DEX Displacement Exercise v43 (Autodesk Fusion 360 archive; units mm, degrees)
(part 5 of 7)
sketch "Sketch38" plane through (0, 0, 0) normal (0, 0, 1) x axis (1, 0, 0)
  line L1 (44.1, 3.35) -> (-44.1, 3.35)
  line L2 (44.1, -3.35) -> (44.1, 3.35)
  line L3 (-44.1, -3.35) -> (44.1, -3.35)
  line L4 (-44.1, 3.35) -> (-44.1, -3.35)
  line L5 (3.35, -35.6) -> (-3.35, -35.6)
  line L6 (3.35, 120) -> (3.35, -35.6)
  line L7 (-3.35, 120) -> (3.35, 120)
  line L8 (-3.35, -35.6) -> (-3.35, 120)
  line L9 (0, 0) -> (-44.1, 0)
  line L10 (0, -3.35) -> (0, 0)
  line L11 (-44.2, 3.45) -> (-34.2, 3.45)
  line L12 (20, -10.75) -> (-20, -10.75)
  line L13 (20, -50.75) -> (20, -10.75)
  line L14 (-20, -50.75) -> (20, -50.75)
  line L15 (-20, -10.75) -> (-20, -50.75)
  line L16 (37.5, 19.4) -> (-37.5, 19.4)
  line L17 (37.5, -95.6) -> (37.5, 19.4)
  line L18 (-37.5, -95.6) -> (37.5, -95.6)
  line L19 (-37.5, 19.4) -> (-37.5, -95.6)
  line L20 (-34.2, 14.95) -> (-34.2, 3.45)
  line L21 (-51.5883, 14.95) -> (-34.2, 14.95)
  line L22 (-44.2, -3.35) -> (-44.2, 3.45)
  line L23 (-56.2229, -3.35) -> (-44.2, -3.35)
  line L24 (-158.6111, -137.8943) -> (-51.5883, 14.95)
  line L25 (-153.1228, -141.7373) -> (-158.6111, -137.8943)
  line L26 (-46.1, 11.107) -> (-153.1228, -141.7373)
  line L27 (-51.5883, 14.95) -> (-46.1, 11.107)
  line L28 (-149.6813, -136.8224) -> (-145.1432, -140)
  line L29 (-144.0466, -148.0925) -> (-153.1228, -141.7373)
  line L30 (-132.575, -131.7095) -> (-144.0466, -148.0925)
  line L31 (-141.6512, -125.3543) -> (-132.575, -131.7095)
  line L32 (-145.1432, -140) -> (-140.6051, -143.1776)
  line L33 (-146.8639, -142.4575) -> (-145.1432, -140)
  line L34 (-53.0452, 12.8694) -> (-47.5569, 9.0264)
  circle C1 centre (-145.1432, -140) radius 7.5
  circle C2 centre (-145.1432, -140) radius 3
  circle C3 centre (-47.5569, 9.0264) radius 0.5
  circle C4 centre (-44.2, 3.45) radius 0.5
  circle C5 centre (-145.1432, -140) radius 4
  point P10 (0, -35.6)
  point P11 (0, -3.35)
  point P12 (-44.1, 0)
  point P13 (-44.1, 0)
  point P15 (0, -3.35)
  point P1 (0, 0)
  point P14 (0, 0)
  point P22 (0, -50.75)
  point P27 (0, -95.6)
  point P5 (-44.1, -3.35)
  point P33 (-145.1432, -140)
  point P38 (-145.1432, -140)
  point P39 (-149.6813, -136.8224)
  point P40 (-147.6007, -138.2793)
  point P43 (-141.6512, -125.3543)
  point P44 (-140.6051, -143.1776)
  point P45 (-140.6051, -143.1776)
  point P46 (-145.1432, -140)
  point P32 (-145.1432, -140)
  point P47 (-145.1432, -140)
  point P48 (-146.8639, -142.4575)
  point P29 (-51.5883, 14.95)
  point P34 (-51.5883, 14.95)
  point P31 (-56.2229, -3.35)
  point P49 (-47.5569, 9.0264)
  point P50 (-53.0452, 12.8694)
  point P51 (-47.5569, 9.0264)
  point P17 (-44.2, 3.45)
  point P52 (-44.2, 3.45)
  point P6 (-3.35, -35.6)
  point P7 (3.35, -35.6)
  point P2 (-44.1, 3.35)
  point P3 (44.1, 3.35)
  point P4 (44.1, -3.35)
  point P20 (20, -50.75)
  point P21 (-20, -50.75)
  point P19 (20, -10.75)
  point P25 (37.5, -95.6)
  point P26 (-37.5, -95.6)
  point P24 (37.5, 19.4)
  point P16 (-34.2, 3.45)
  point P28 (-34.2, 14.95)
  point P37 (-46.1, 11.107)
  horizontal L1
  vertical L2
  horizontal L3
  vertical L4
  horizontal L5
  vertical L6
  horizontal L7
  vertical L8
  equal L4 L5
  midpoint L5 P10
  coincident L3 P11
  vertical P10 P11
  midpoint L4 P12
  coincident P12 P13
  perpendicular L8 L9
  perpendicular L9 L10
  coincident P11 P15
  coincident P1 P14
  midpoint L3 P11
  perpendicular L8 L11
  horizontal L12
  vertical L13
  horizontal L14
  vertical L15
  midpoint L14 P22
  vertical P1 P22
  horizontal L16
  vertical L17
  horizontal L18
  vertical L19
  midpoint L18 P27
  vertical P1 P27
  perpendicular L11 L20
  perpendicular L20 L21
  perpendicular L11 L22
  concentric C1 C2
  horizontal L23
  coincident P5 L23
  perpendicular L24 L25
  parallel L24 L26
  parallel L25 L27
  coincident P33 P38
  coincident L26 P39
  perpendicular L26 L28
  coincident C2 P40
  coincident L28 P40
  perpendicular L26 L29
  perpendicular L29 L30
  perpendicular L30 L31
  coincident L26 P43
  coincident L28 P44
  coincident P44 P45
  coincident P33 P46
  equal L28 L32
  coincident P32 P47
  coincident C2 P48
  perpendicular L28 L33
  coincident P29 P34
  coincident P31 L26
  coincident L26 P49
  coincident L24 P50
  perpendicular L24 L34
  coincident P49 P51
  coincident P17 P52
  equal C3 C4
  coincident L30 P44
  concentric C2 C5
  dimension "d1464" distance P6 P7 = 6.7 (= "t_sheet_MAIN")
  dimension "d1465" distance P10 P12 = 35.6
  dimension "d1466" distance P2 P3 = 88.2 (= "( 29.1 * 2 ) * 1 mm + 30 mm")
  dimension "d1467" distance P1 L7 = 120
  dimension "d1468" distance P4 L12 = 7.4
  dimension "d1469" distance P20 P21 = 40
  dimension "d1470" distance P19 P20 = 40
  dimension "d1471" distance P25 P26 = 75
  dimension "d1472" distance P24 P25 = 115
  dimension "d1473" distance P7 L16 = 55
  dimension "d1474" distance P12 L22 = 0.1
  dimension "d1476" distance L1 L11 = 0.1 (= "d1475")
  dimension "d1478" distance P16 P28 = 11.5
  dimension "d1489" diameter C2 = 6 (= "hw_m4insert_d")
  dimension "d1491" diameter C1 = 15
  dimension "d1502" distance L24 L26 = 6.7 (= "t_sheet_MAIN")
  dimension "d1503" = 110
  dimension "d1504" distance P1 P32 = 140
  dimension "d1506" distance L26 P40 = 2.54
  dimension "d1531" angle L15 L26 = 35
  dimension "d1532" distance P12 P37 = 2
  dimension "d1533" distance P2 L20 = 9.9
  dimension "d1541" distance P37 L34 = 2.54
  dimension "d1557" diameter C3 = 1
  dimension "d1576" distance L29 L31 = 20
  dimension "d1577" distance L29 L32 = 6
  dimension "d1583" distance C2 C5 = 1
  dimension "d1441" leftDistance = 1.7
  dimension "d1442" leftDistance = 1
  dimension "d1443" leftDistance = 0.5
  dimension "d1445" leftDistance = 0.5
  dimension "d1446" rightDistance = 1.5
  dimension "d1447" leftDistance = 0.5
  dimension "d1449" distance = 5
  dimension "d1450" distance = 15
  dimension "d1452" distance = 5
  dimension "d1453" distance = 4.9
  dimension "d1454" distance = 4.9
  dimension "d1455" distance = 5
  dimension "d1456" distance = 24.9
  dimension "d531" countU = 13 (= "nh_gantry_length + 1")
  dimension "d532" CountV = 9 (= "nh_gantry_width + 1")
  dimension "d533" uSpaceDistance = 10
  dimension "d534" vSpaceDistance = -10
  dimension "d535" diameter = 3.3 (= "hw_m4_tappedwj")
  dimension "d541" uSpaceDistance = 10
  dimension "d542" vSpaceDistance = 10
  dimension "d560" distance = 6.6 (= "t_sheet_MAIN")
  dimension "d563" distance = 5 (= "t_bearings")
  dimension "d564" distance = 16 (= "od_bearings")
  dimension "d565" angle = 45 (= "d566")
  dimension "d566" angle = 45
  dimension "d567" distance = 10 (= "l_shoulder_thread")
  dimension "d568" distance = 6.6 (= "t_sheet_MAIN")
  dimension "d569" distance = 45 (= "( ( nh_gantry_width * 10 ) * 1 mm + 10 mm ) / 2")
  dimension "d571" distance = 4.5 (= "hw_shoulder_headHeight + 0.5 mm")
  dimension "d572" distance = 4.5 (= "hw_shoulder_headDiameter / 2")
  dimension "d574" distance = 8.8037
  dimension "d576" distance = 0.5
  dimension "d577" distance = 0.5
  dimension "d580" distance = 0.5
  dimension "d581" distance = 3.5 (= "hw_m4insert_d / 2 + 0.5 mm")
  dimension "d582" distance = 3.5 (= "d581")
  dimension "d583" distance = 2.1
  dimension "d584" distance = 0.8383
  dimension "d586" distance = 1.269 (= "0.5 mm + 0.769 mm")
  dimension "d587" distance = 5
  dimension "d588" distance = 10
  dimension "d589" distance = 5
  dimension "d590" AlongDistance = 65 (= "( nh_gantry_length * 10 + 10 ) / 2 * 1 mm")
  dimension "d591" TaperAngle = 0
  dimension "d597" ProfileOffset = 0.25 (= "carriage_offsets")
  dimension "d599" TaperAngle = 0
  dimension "d601" diameter = 16 (= "od_bearings")
  dimension "d602" diameter = 6 (= "hw_m4insert_d")
  dimension "d603" diameter = 4
  dimension "d604" distance = 0.25
  dimension "d606" AlongDistance = -20
  dimension "d607" TaperAngle = 0
  dimension "d608" ProfileOffset = 0.5
  dimension "d609" AlongDistance = 5 (= "t_bearings")
  dimension "d610" TaperAngle = 0
  dimension "d612" distance = 0.25
  dimension "d613" diameter = 4
  dimension "d614" diameter = 6 (= "hw_m4insert_d")
  dimension "d615" diameter = 16 (= "od_bearings")
  dimension "d616" AlongDistance = -20
  dimension "d617" TaperAngle = 0
  dimension "d618" ProfileOffset = 0.5
  dimension "d619" AlongDistance = 5 (= "t_bearings")
  dimension "d620" TaperAngle = 0
  dimension "d621" AlongDistance = 670 (= "l_actual_complete")
  dimension "d622" TaperAngle = 0
  dimension "d623" distance = 0.1
  dimension "d624" distance = 1.6455
  dimension "d625" distance = 3.4128
  dimension "d626" distance = 13.2 (= "0.5 in + 0.5 mm")
  dimension "d628" distance = 5
  dimension "d630" distance = 30
  dimension "d631" diameter = 4.064 (= "hw_n6_thru")
  dimension "d636" diameter = 6.6548 (= "hw_n6_flathead")
  dimension "d637" diameter = 3.1 (= "hw_n6_thread")
  dimension "d638" distance = 4
  dimension "d639" distance = 4 (= "d638")
  dimension "d641" TaperAngle = 0
  dimension "d642" ProfileOffset = 0
  dimension "d643" Side1Offset = 0
  dimension "d644" TaperAngle = 0
  dimension "d645" ProfileOffset = 0
  dimension "d646" Side1Offset = 0
  dimension "d647" TaperAngle = 0
  dimension "d648" distance = 5
  dimension "d649" distance = 0.75
  dimension "d650" ProfileOffset = 0
  dimension "d651" Side1Offset = 0
  dimension "d652" TaperAngle = 0
  dimension "d653" AlongDistance = 21
  dimension "d654" TaperAngle = 0
  dimension "d655" distance = 1
  dimension "d656" ProfileOffset = 0
  dimension "d657" Side1Offset = 0
  dimension "d658" TaperAngle = 0
  dimension "d659" AlongDistance = 12
  dimension "d660" TaperAngle = 0
  dimension "d661" Side1Offset = 0
  dimension "d662" TaperAngle = 0
  dimension "d667" Radius = 4
  dimension "d669" Radius = 4
  dimension "d670" Radius = 1
  dimension "d673" Radius = 0.5
  dimension "d674" Radius = 0.5
  dimension "d675" Radius = 0.5
  dimension "d676" Radius = 0.5
  dimension "d677" Radius = 0.2
  dimension "d680" distance = 40
  dimension "d681" distance = 6
  dimension "d691" distance = 2.54
  dimension "d692" distance = 0.5 (= "d689")
  dimension "d693" distance = 0.5
  dimension "d696" distance = 0.5
  dimension "d697" distance = 5
  dimension "d701" distance = 1.7
  dimension "d702" distance = 1.7 (= "d701")
  dimension "d706" distance = 2.54 (= "d691")
  dimension "d707" distance = 3.5
  dimension "d708" distance = 0.5
  dimension "d709" ProfileOffset = 0
  dimension "d710" Side1Offset = 0
  dimension "d711" TaperAngle = 0
  dimension "d712" ProfileOffset = 0
  dimension "d713" Side1Offset = 5
  dimension "d714" TaperAngle = 0
  dimension "d715" Side1Offset = 0
  dimension "d716" TaperAngle = 0
  dimension "d717" distance = 0.75
  dimension "d718" distance = 1.7
  dimension "d719" diameter = 16 (= "od_bearings")
  dimension "d720" diameter = 6 (= "hw_m4insert_d")
  dimension "d721" diameter = 4
  dimension "d722" distance = 0.25
  dimension "d723" AlongDistance = -19
  dimension "d724" TaperAngle = 0
  dimension "d725" distance = 1
  dimension "d726" ProfileOffset = 0.5
  dimension "d727" AlongDistance = 5 (= "t_bearings")
  dimension "d728" TaperAngle = 0
  dimension "d729" diameter = 4
  dimension "d730" diameter = 6 (= "hw_m4insert_d")
  dimension "d731" diameter = 16 (= "od_bearings")
  dimension "d732" distance = 1
  dimension "d733" distance = 0.25
  dimension "d734" AlongDistance = -26
  dimension "d735" TaperAngle = 0
  dimension "d736" ProfileOffset = 0.5
  dimension "d737" AlongDistance = 5 (= "t_bearings")
  dimension "d738" TaperAngle = 0
  dimension "d739" distance = 6
  dimension "d740" ProfileOffset = 0
  dimension "d741" Side1Offset = 0
  dimension "d742" TaperAngle = 0
  dimension "d743" Radius = 4
  dimension "d744" distance = -1
  dimension "d745" AlongDistance = 32
  dimension "d746" TaperAngle = 0
  dimension "d747" distance = 0.5
  dimension "d748" distance = 1
  dimension "d749" ProfileOffset = 0
  dimension "d750" AlongDistance = 3
  dimension "d751" TaperAngle = 0
  dimension "d752" ProfileOffset = 0
  dimension "d753" Side1Offset = 0
  dimension "d754" TaperAngle = 0
  dimension "d755" Side1Offset = 0
  dimension "d756" TaperAngle = 0
  dimension "d757" ProfileOffset = 0
  dimension "d758" Side1Offset = 0
  dimension "d759" TaperAngle = 0
  dimension "d760" AlongDistance = 12
  dimension "d761" TaperAngle = 0
  dimension "d762" AlongDistance = -37
  dimension "d763" TaperAngle = 0
  dimension "d764" Side1Offset = 0.5
  dimension "d765" TaperAngle = 0
  dimension "d767" Radius = 3
  dimension "d768" Radius = 2
  dimension "d770" Radius = 3
  dimension "d771" Radius = 3
  dimension "d772" distance = 3
  dimension "d773" distance = 3
  dimension "d774" Radius = 1
  dimension "d775" Radius = 0.5
  dimension "d776" Radius = 2
  dimension "d777" diameter = 5.4 (= "hw_m3insert_d")
  dimension "d778" diameter = 3.5 (= "hw_m3_thru")
  dimension "d779" Side1Offset = 0
  dimension "d780" TaperAngle = 0
  dimension "d781" Side1Offset = 0
  dimension "d782" TaperAngle = 0
  dimension "d783" Radius = 2
  dimension "d784" Radius = 2
  dimension "d785" Radius = 2
  dimension "d786" Radius = 3
  dimension "d788" Radius = 0.5
  dimension "d789" distance = 12
  dimension "d790" distance = 2
  dimension "d791" angle = 45
  dimension "d793" Radius = 2
  dimension "d794" Radius = 2
  dimension "d795" Radius = 1
  dimension "d797" Radius = 2
  dimension "d798" Radius = 1
  dimension "d799" Radius = 2
  dimension "d800" Radius = 4.5
  dimension "d801" distance = 0.275 (= "preload_bearings / 2")
  dimension "d803" distance = -0.5
  dimension "d806" distance = 3
  dimension "d807" AlongDistance = -60
  dimension "d808" distance = 3.8274 (= "d430 / 2")
  dimension "d809" distance = 0.423 (= "1 mm - 0.577 mm")
  dimension "d810" distance = 0.5
  dimension "d813" Side1Offset = 0
  dimension "d814" TaperAngle = 0
  dimension "d815" distance = 0.1
  dimension "d816" distance = 1.75
  dimension "d818" distance = 35
  dimension "d820" distance = 5
  dimension "d821" distance = 5
  dimension "d822" diameter = 4.064 (= "hw_n6_thru")
  dimension "d823" diameter = 6.6548 (= "hw_n6_flathead")
  dimension "d824" distance = 0.6
  dimension "d825" distance = 0.6 (= "d824")
  dimension "d827" TaperAngle = 0
  dimension "d828" diameter = 3.1 (= "hw_n6_thread")
  dimension "d829" Side1Offset = 0
  dimension "d830" TaperAngle = 0
  dimension "d831" distance = 4
  dimension "d832" distance = 4.477 (= "d833")
  dimension "d833" distance = 4.477 (= "d477")
  dimension "d836" diameter = 6.6548 (= "hw_n6_flathead")
  dimension "d839" Side1Offset = 0
  dimension "d840" TaperAngle = 0
  dimension "d841" distance = 0.9
  dimension "d842" angle = 50
  dimension "d843" angle = 50
  dimension "d844" distance = 8
  dimension "d845" distance = 5
  dimension "d846" diameter = 4.5
  dimension "d847" AlongDistance = -7
  dimension "d848" TaperAngle = 0
  dimension "d849" leftDistance = 0.75
  dimension "d850" ProfileOffset = 0
  dimension "d851" Side1Offset = 0
  dimension "d852" TaperAngle = 0
  dimension "d853" ProfileOffset = 0
  dimension "d854" Side1Offset = 0
  dimension "d855" TaperAngle = 0
  dimension "d856" distance = 12.7
  dimension "d857" leftDistance = 1.5
  dimension "d858" distance = 1.5454
  dimension "d859" Radius = 4
  dimension "d860" Radius = 2
  dimension "d861" Radius = 2
  dimension "d862" Radius = 4
  dimension "d863" Radius = 2
  dimension "d864" Radius = 35
  dimension "d865" Radius = 4
  dimension "d866" Radius = 1
  dimension "d869" Side1Offset = 0
  dimension "d870" TaperAngle = 0
  dimension "d872" distance = 1.5
  dimension "d873" leftDistance = 1.5
  dimension "d874" Radius = 2
  dimension "d885" distance = 27.775
  dimension "d886" distance = 30.275 (= "30 mm + preload_bearings / 2")
  dimension "d889" diameter = 3.3 (= "hw_m4_tappedwj")
  dimension "d890" distance = 5
  dimension "d891" distance = 10.275 (= "10 mm + preload_bearings / 2")
  dimension "d893" TaperAngle = 0
  dimension "d894" distance = 17.5
  dimension "d895" distance = 27.5
  dimension "d896" distance = 0.2
  dimension "d897" distance = 0.2 (= "d896")
  dimension "d900" distance = 6
  dimension "d902" distance = 3.7 (= "2 mm + 1.2 mm + 0.5 mm")
  dimension "d903" distance = 1
  dimension "d904" distance = 8
  dimension "d905" distance = 2.54
  dimension "d906" distance = 2.54
  dimension "d907" distance = 2.54
  dimension "d908" Side1Offset = 0
  dimension "d909" TaperAngle = 0
  dimension "d910" ProfileOffset = 0
  dimension "d911" Side1Offset = 0
  dimension "d912" TaperAngle = 0
  dimension "d913" leftDistance = 1.5
  dimension "d915" distance = 5.65
  dimension "d916" distance = 14.65
  dimension "d917" distance = 14.65
  dimension "d918" Side1Offset = 0
  dimension "d919" TaperAngle = 0
  dimension "d920" ChordLen = 4
  dimension "d921" ChordLen = 1
  dimension "d923" distance = 2.54
  dimension "d924" Radius = 2
extrude "Extrude159" new body sketch "Sketch38" profile of L11 L20 L21 L22 L23 L24 L26 L27 L34 C3 C4 along normal blind 40
extrude "Extrude160" sketch "Sketch38" profile of C1 L24 L25 L26 L34 to an object offset -25
sketch "Sketch40" plane through (-41.6405, 29.157, 0) normal (-0.8192, 0.5736, 0) x axis (-0.5736, -0.8192, 0)
  line L1 (203.932, -25) -> (19.8835, -25)
  line L2 (203.932, 40) -> (203.932, -25)
  line L3 (183.932, -5) -> (203.932, -5)
  line L4 (34.9923, 40) -> (183.932, -5)
  line L5 (183.932, -25) -> (17.3435, 0)
  line L6 (34.9923, 40) -> (34.9923, 0)
  line L7 (183.932, -25) -> (183.932, -5)
  line L8 (19.8835, 40) -> (203.932, 40)
  line L9 (19.8835, -25) -> (19.8835, 40)
  point P7 (203.932, -5)
  point P4 (17.3435, 0)
  point P10 (17.3435, 0)
  point P11 (183.932, -25)
  point P8 (183.932, -5)
  point P9 (34.9923, 40)
  point P13 (34.9923, 40)
  point P6 (203.932, -25)
  coincident L2 P7
  perpendicular L2 L3
  coincident P4 P10
  coincident L1 P11
  vertical P8 P11
  coincident P9 P13
  dimension "d1521" distance P6 P11 = 20
  dimension "d1522" distance P6 L3 = 20
extrude "Extrude161" cut sketch "Sketch40" profile of L1 L2 L3 L4 L5 along a picked direction no distance stored
extrude "Extrude162" sketch "Sketch40" profile of L1 L2 L3 L7 to an object
extrude "Extrude163" sketch "Sketch38" profile of C1 C2 L26 L30 blind -15 from offset -0.5
sketch "Sketch41" plane through (0, 3.45, 0) normal (0, -1, 0) x axis (1, 0, 0)
  line L1 (-34.2, 0) -> (-43.7, 0)
  line L2 (-34.2, 40) -> (-34.2, 0)
  line L3 (-43.7, 40) -> (-34.2, 40)
  line L4 (-43.7, 0) -> (-43.7, 40)
  circle C1 centre (-39.1, 5) radius 2.7
  circle C2 centre (-39.1, 35) radius 2.7
  point P6 (-39.1, 5)
  point P7 (-39.1, 35)
  vertical P6 P7
  equal C1 C2
  dimension "d1534" distance L3 P7 = 5
  dimension "d1536" distance L1 P6 = 5
  dimension "d1537" = 20
  dimension "d1538" diameter C2 = 5.4 (= "hw_m3insert_d")
extrude "Extrude164" cut sketch "Sketch41" profile of C1 C2 to an object
sketch "Sketch42" plane through (-36.1522, 25.314, 0) normal (-0.8192, 0.5736, 0) x axis (-0.5736, -0.8192, 0)
  line L1 (34.9923, 0) -> (20.3835, 0)
  line L2 (34.9923, 40) -> (34.9923, 0)
  line L3 (20.3835, 40) -> (34.9923, 40)
  line L4 (20.3835, 0) -> (20.3835, 40)
  circle C1 centre (27.9923, 35) radius 2.7
  circle C2 centre (27.9923, 5) radius 2.7
  circle C3 centre (27.9923, 5) radius 1.575
  circle C4 centre (27.9923, 35) radius 1.575
  point P6 (27.9923, 35)
  point P7 (27.9923, 5)
  vertical P6 P7
  equal C1 C2
  concentric C2 C3
  concentric C1 C4
  equal C3 C4
  dimension "d1544" distance L3 P6 = 5
  dimension "d1545" distance L1 P7 = 5
  dimension "d1546" distance L2 P7 = 7
  dimension "d1547" diameter C1 = 5.4 (= "hw_m3insert_d")
  dimension "d1548" diameter C4 = 3.15
extrude "Extrude165" cut sketch "Sketch42" profile of C1 C2 C3 C4 along a picked direction blind -6
chamfer "Chamfer37" distance 0.5
extrude "Extrude166" cut sketch "Sketch42" profile of C3 C4 along a picked direction blind 6.7 (= "t_sheet_MAIN")
fillet "Fillet111" radius 4
fillet "Fillet112" radius 2
fillet "Fillet113" radius 2
fillet "Fillet114" radius 0.4
fillet "Fillet115" radius 0.4
sketch "Sketch43" plane through (-27.076, 18.9588, 0) normal (0.8192, -0.5736, 0) x axis (0.5736, 0.8192, 0)
  line L1 (-183.932, -25) -> (-203.932, -25)
  line L2 (-183.932, -5) -> (-183.932, -25)
  line L3 (-203.932, -5) -> (-183.932, -5)
  line L4 (-203.932, -25) -> (-203.932, -5)
  circle C1 centre (-188.932, -20) radius 2.7
  circle C2 centre (-198.932, -10) radius 2.7
  circle C3 centre (-188.932, -20) radius 1.575
  circle C4 centre (-198.932, -10) radius 1.575
  point P8 (-188.932, -20)
  point P9 (-198.932, -10)
  point P6 (-188.932, -20)
  point P7 (-198.932, -10)
  equal C1 C2
  concentric C1 C3
  concentric C2 C4
  equal C3 C4
  dimension "d1560" diameter C1 = 5.4 (= "hw_m3insert_d")
  dimension "d1561" diameter C3 = 3.15
  dimension "d1563" distance L1 P8 = 5 (= "d1562")
  dimension "d1565" distance L3 P9 = 5
  dimension "d1578" distance L2 P6 = 5
  dimension "d1579" distance L4 P7 = 5
extrude "Extrude167" cut sketch "Sketch43" profile of C3 C4 along a picked direction to an object
extrude "Extrude168" cut sketch "Sketch43" profile of C1 C2 C3 C4 along a picked direction blind -6
chamfer "Chamfer38" distance 1
chamfer "Chamfer39" distance 0.5
extrude "Extrude170" sketch "Sketch38" profile of C2 blind 11
extrude "Extrude171" sketch "Sketch38" profile of C2 C5 blind -0.5
combine "Combine23"
chamfer "Chamfer40" distance 0.5
chamfer "Chamfer41" distance 0.5
fillet "Fillet116" radius 2
fillet "Fillet117" radius 1
mirror "Mirror13"

design "rct-lb-gt3-endmatter"
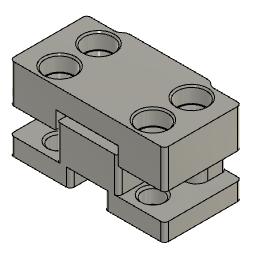
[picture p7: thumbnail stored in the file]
parameter "t_sheet_MAIN" = 6.7 comment "thickness of *most* of the gantry material"
parameter "t_sheet_SECOND" = 6.35 (= "1 / 4 * 1") comment "thickness of the webs"
parameter "od_bearings" = 16
parameter "id_bearings" = 5
parameter "t_bearings" = 5
parameter "p_belt" = 2
parameter "w_belt" = 10
parameter "t_belt" = 1.4
parameter "l_top_belt_to_rail" = 3
parameter "r_cutoutTool" = 2.05 (= "4.1 mm / 2")
parameter "hw_m3_thru" = 3.5
parameter "hw_m3_head" = 5.5
parameter "hw_m3_washer" = 7
parameter "hw_m3_thread" = 2.5
parameter "tab_breather" = 0.2 comment "tab clearance"
parameter "hw_m5_thread" = 4.2
parameter "hw_m5_head" = 8.5
parameter "hw_m5_washer" = 10
parameter "hw_m5_thru" = 5.25
parameter "hw_m6_thru" = 6.5
parameter "hw_m6_head" = 10
parameter "hw_m6_washer" = 12
parameter "l_beltblock" = 15
parameter "hw_plstf6_thread" = 2.94
parameter "hw_plstf6_thru" = 4
parameter "hw_plstf6_head" = 6.86
parameter "hw_plstf6_washer" = 7.92
parameter "hw_m3_flathead" = 6
parameter "hw_m4insert_d" = 6
parameter "hw_m4insert_l" = 4.8
parameter "hw_m4_tappedwj" = 3.3
parameter "hw_m4_thru" = 4.25
parameter "hw_m4_head" = 7
parameter "hw_m4_headheight" = 4
parameter "preload_bearings" = 0.55
parameter "hw_m3insert_d" = 5.4
parameter "hw_m3insert_l" = 3.8
parameter "dist_clearance" = 0.5
parameter "hw_shoulder_headDiameter" = 9
parameter "hw_shoulder_headHeight" = 4
parameter "l_travel" = 405 comment "will be rounded to 10s"
parameter "User Parameter" = 0 (= "min 10")
parameter "nh_rail_width" = "nh_gantry_width - 3"
parameter "l_shoulder_thread" = 10
parameter "hw_n6_thru" = 4.064
parameter "hw_n6_thread" = 3.1
parameter "hw_n6_flathead" = 6.6548
parameter "hw_n6_head" = 6.858
parameter "carriage_offsets" = 0.25
parameter "hw_momentPin_reald" = 3.683
parameter "pinch_by" = 0.2
parameter "d285" = 2
parameter "d344" = 3.5
parameter "d482" = 3.35 (= "t_sheet_MAIN / 2")
parameter "d578" = 0.5
parameter "d683" = 3.683 (= "hw_momentPin_reald")
parameter "d689" = 0.5
parameter "d698" = 5
parameter "d705" = 3.5415 (= "d683 / 2 + 1.7 mm")
parameter "d837" = 0.25
sketch "Sketch32" plane through (0, 0, 0) normal (0, 0, 1) x axis (1, 0, 0)
  line L1 (19.9, 0) -> (0, 0)
  line L2 (19.9, 21) -> (19.9, 0)
  line L3 (0, 21) -> (19.9, 21)
  line L4 (0, 0) -> (0, 21)
  line L5 (7.5, 0) -> (7.5, 21)
  line L6 (8, 12) -> (19.9, 12)
  line L7 (8, 0) -> (8, 12)
  line L8 (16, 21) -> (16, 12)
  line L9 (12, 19.8) -> (19.9, 19.8)
  line L10 (10.8, 21) -> (12, 19.8)
  circle C1 centre (12, 4.9) radius 2.7
  circle C2 centre (12, 14.9) radius 2.7
  circle C3 centre (12, 14.9) radius 1.575
  circle C4 centre (12, 4.9) radius 1.575
  circle C5 centre (12, 4.9) radius 3.75
  circle C6 centre (12, 14.9) radius 3.75
  point P1 (0, 0)
  point P2 (0, 0)
  point P6 (7.5, 21)
  point P7 (7.5, 0)
  point P8 (12, 4.9)
  point P9 (12, 14.9)
  point P12 (8, 0)
  point P10 (19.9, 12)
  point P15 (12, 13.325)
  point P13 (12, 14.9)
  point P16 (16, 12)
  point P17 (16, 21)
  point P20 (19.9, 19.8)
  point P22 (10.8, 21)
  point P19 (12, 14.9)
  point P21 (12, 19.8)
  point P3 (19.9, 0)
  horizontal L1
  vertical L2
  horizontal L3
  vertical L4
  coincident P1 P2
  coincident L3 P6
  coincident L1 P7
  perpendicular L1 L5
  equal C1 C2
  vertical P8 P9
  perpendicular L2 L6
  coincident L1 P12
  perpendicular L1 L7
  concentric C2 C3
  concentric C1 C4
  equal C3 C4
  coincident L2 P10
  coincident C3 P15
  vertical P13 P15
  coincident L6 P16
  coincident L3 P17
  perpendicular L3 L8
  concentric C4 C5
  concentric C3 C6
  equal C5 C6
  coincident L2 P20
  perpendicular L8 L9
  coincident L3 P22
  vertical P19 P21
  dimension "d1252" distance P1 L5 = 7.5 (= "( 15 / 2 ) * 1 mm")
  dimension "d1253" diameter C2 = 5.4 (= "hw_m3insert_d")
  dimension "d1254" distance P1 P8 = 12
  dimension "d1255" distance P1 L2 = 19.9 (= "( 39.8 / 2 ) * 1 mm")
  dimension "d1256" distance L5 L7 = 0.5
  dimension "d1257" distance P8 P9 = 10
  dimension "d1258" distance P3 P8 = 4.9
  dimension "d1259" = 4.9
  dimension "d1260" diameter C3 = 3.15
  dimension "d1261" = 1.7
  dimension "d1262" distance P1 L8 = 16
  dimension "d1272" diameter C6 = 7.5
  dimension "d1304" distance P1 L3 = 21 (= "( 3 * 7 ) * 1 mm")
  dimension "d1306" distance P19 L9 = 4.9
  dimension "d1307" angle L9 L10 = 45
  dimension "d1326" distance P3 L6 = 12
  dimension "d485" distance = 0.75 (= "d480")
  dimension "d487" diameter = 3.1 (= "hw_n6_thread")
  dimension "d488" diameter = 4.064 (= "hw_n6_thru")
  dimension "d497" distance = 9
  dimension "d498" angle = 5 (= "d469")
  dimension "d500" distance = 5
  dimension "d501" radius = 11.075 (= "( 22.15 / 2 ) * 1 mm")
  dimension "d504" diameter = 5.3 (= "hw_m3insert_d - 0.1 mm")
  dimension "d506" diameter = 3.5 (= "hw_m3_thru")
  dimension "d535" diameter = 3.3 (= "hw_m4_tappedwj")
  dimension "d560" distance = 6.6 (= "t_sheet_MAIN")
  dimension "d563" distance = 5 (= "t_bearings")
  dimension "d564" distance = 16 (= "od_bearings")
  dimension "d565" angle = 45 (= "d566")
  dimension "d566" angle = 45
  dimension "d567" distance = 10 (= "l_shoulder_thread")
  dimension "d568" distance = 6.6 (= "t_sheet_MAIN")
  dimension "d569" distance = 45 (= "( ( nh_gantry_width * 10 ) * 1 mm + 10 mm ) / 2")
  dimension "d571" distance = 4.5 (= "hw_shoulder_headHeight + 0.5 mm")
  dimension "d572" distance = 4.5 (= "hw_shoulder_headDiameter / 2")
  dimension "d574" distance = 8.8037
  dimension "d576" distance = 0.5
  dimension "d577" distance = 0.5
  dimension "d580" distance = 0.5
  dimension "d581" distance = 3.5 (= "hw_m4insert_d / 2 + 0.5 mm")
  dimension "d582" distance = 3.5 (= "d581")
  dimension "d583" distance = 2.1
  dimension "d584" distance = 0.8383
  dimension "d586" distance = 1.269 (= "0.5 mm + 0.769 mm")
  dimension "d587" distance = 5
  dimension "d588" distance = 10
  dimension "d589" distance = 5
  dimension "d601" diameter = 16 (= "od_bearings")
  dimension "d602" diameter = 6 (= "hw_m4insert_d")
  dimension "d603" diameter = 4
  dimension "d604" distance = 0.25
  dimension "d612" distance = 0.25
  dimension "d613" diameter = 4
  dimension "d614" diameter = 6 (= "hw_m4insert_d")
  dimension "d615" diameter = 16 (= "od_bearings")
  dimension "d623" distance = 0.1
  dimension "d624" distance = 1.6455
  dimension "d625" distance = 3.4128
  dimension "d626" distance = 13.2 (= "0.5 in + 0.5 mm")
  dimension "d628" distance = 5
  dimension "d630" distance = 30
  dimension "d631" diameter = 4.064 (= "hw_n6_thru")
  dimension "d636" diameter = 6.6548 (= "hw_n6_flathead")
  dimension "d637" diameter = 3.1 (= "hw_n6_thread")
  dimension "d638" distance = 4
  dimension "d639" distance = 4 (= "d638")
  dimension "d648" distance = 5
  dimension "d649" distance = 0.75
  dimension "d655" distance = 1
  dimension "d680" distance = 40
  dimension "d681" distance = 6
  dimension "d691" distance = 2.54
  dimension "d692" distance = 0.5 (= "d689")
  dimension "d693" distance = 0.5
  dimension "d696" distance = 0.5
  dimension "d697" distance = 5
  dimension "d701" distance = 1.7
  dimension "d702" distance = 1.7 (= "d701")
  dimension "d706" distance = 2.54 (= "d691")
  dimension "d707" distance = 3.5
  dimension "d708" distance = 0.5
  dimension "d717" distance = 0.75
  dimension "d718" distance = 1.7
  dimension "d719" diameter = 16 (= "od_bearings")
  dimension "d720" diameter = 6 (= "hw_m4insert_d")
  dimension "d721" diameter = 4
  dimension "d722" distance = 0.25
  dimension "d725" distance = 1
  dimension "d729" diameter = 4
  dimension "d730" diameter = 6 (= "hw_m4insert_d")
  dimension "d731" diameter = 16 (= "od_bearings")
  dimension "d732" distance = 1
  dimension "d733" distance = 0.25
  dimension "d739" distance = 6
  dimension "d747" distance = 0.5
  dimension "d748" distance = 1
  dimension "d777" diameter = 5.4 (= "hw_m3insert_d")
  dimension "d778" diameter = 3.5 (= "hw_m3_thru")
  dimension "d789" distance = 12
  dimension "d790" distance = 2
  dimension "d791" angle = 45
  dimension "d801" distance = 0.275 (= "preload_bearings / 2")
  dimension "d806" distance = 3
  dimension "d807" AlongDistance = -60
  dimension "d808" distance = 3.8274 (= "d430 / 2")
  dimension "d809" distance = 0.423 (= "1 mm - 0.577 mm")
  dimension "d810" distance = 0.5
  dimension "d815" distance = 0.1
  dimension "d816" distance = 1.75
  dimension "d818" distance = 35
  dimension "d820" distance = 5
  dimension "d821" distance = 5
  dimension "d822" diameter = 4.064 (= "hw_n6_thru")
  dimension "d823" diameter = 6.6548 (= "hw_n6_flathead")
  dimension "d824" distance = 0.6
  dimension "d825" distance = 0.6 (= "d824")
  dimension "d828" diameter = 3.1 (= "hw_n6_thread")
  dimension "d831" distance = 4
  dimension "d832" distance = 4.477 (= "d833")
  dimension "d833" distance = 4.477 (= "d477")
  dimension "d836" diameter = 6.6548 (= "hw_n6_flathead")
  dimension "d841" distance = 0.9
  dimension "d842" angle = 50
  dimension "d843" angle = 50
  dimension "d844" distance = 8
  dimension "d845" distance = 5
  dimension "d846" diameter = 4.5
  dimension "d856" distance = 12.7
  dimension "d858" distance = 1.5454
  dimension "d872" distance = 1.5
  dimension "d885" distance = 27.775
  dimension "d886" distance = 30.275 (= "30 mm + preload_bearings / 2")
  dimension "d889" diameter = 3.3 (= "hw_m4_tappedwj")
  dimension "d890" distance = 5
  dimension "d891" distance = 10.275 (= "10 mm + preload_bearings / 2")
  dimension "d894" distance = 17.5
  dimension "d895" distance = 27.5
  dimension "d896" distance = 0.2
  dimension "d897" distance = 0.2 (= "d896")
  dimension "d900" distance = 6
  dimension "d902" distance = 3.7 (= "2 mm + 1.2 mm + 0.5 mm")
  dimension "d903" distance = 1
  dimension "d904" distance = 8
  dimension "d905" distance = 2.54
  dimension "d906" distance = 2.54
  dimension "d907" distance = 2.54
  dimension "d915" distance = 5.65
  dimension "d916" distance = 14.65
  dimension "d917" distance = 14.65
  dimension "d923" distance = 2.54
extrude "Extrude131" new body sketch "Sketch32" profile of L1 L2 L3 L4 C1 C2 L6 L7 C3 C4 L8 C5 C6 L9 L10 along normal blind 4.5
extrude "Extrude132" sketch "Sketch32" profile of L1 L3 L4 C2 L6 L7 C3 L8 C6 L9 L10 blind 6.7 (= "t_sheet_MAIN")
extrude "Extrude133" sketch "Sketch32" profile of L1 L2 L3 L4 C1 C2 L6 L7 C3 C4 L8 C5 C6 L9 L10 blind 10
extrude "Extrude134" cut sketch "Sketch32" profile of C3 C4 no distance stored
extrude "Extrude135" sketch "Sketch32" profile of C1 C2 L6 C3 C4 C5 C6 blind -4
extrude "Extrude136" cut sketch "Sketch32" profile of C1 C2 C3 C4 along normal blind 4.5
sketch "Sketch33" plane through (0, 0, 0) normal (-1, 0, 0) x axis (0, -1, 0)
  line L1 (0, 0) -> (-21, 0)
  line L2 (0, 21.2) -> (0, 0)
  line L3 (-21, 0) -> (-21, 21.2)
  line L4 (-19.8, 4.5) -> (0, 4.5)
  line L5 (0, 13.5) -> (-21, 13.5)
  line L6 (-21, 21.2) -> (0, 21.2)
  line L7 (-19.5, 14.76) -> (-19.8489, 14.76)
  line L8 (-19.5, 13.5) -> (-19.5, 14.76)
  line L9 (-12, 11.2) -> (0, 11.2)
  line L10 (-21, 11.2) -> (-12, 11.2)
  line L11 (-21, 11.3) -> (0, 11.3)
  line L12 (-21, 4.5) -> (-19.8, 4.5)
  arc A1 centre (-21, 15.05) radius 0.85 clockwise from (-21, 15.9) to (-20.2388, 15.4283)
  arc A2 centre (-19.8489, 15.01) radius 0.25 clockwise from (-19.8489, 14.76) to (-20.0963, 14.9735)
  arc A3 centre (-21.6, 14.7518) radius 1.52 clockwise from (-20.2388, 15.4283) to (-20.0963, 14.9735)
  point P8 (-21, 13.5)
  point P9 (0, 13.5)
  point P10 (-21, 15.9)
  point P12 (-21, 15.05)
  point P15 (-19.5, 13.5)
  point P11 (-20.2388, 15.4283)
  point P18 (-20.2388, 15.4283)
  point P16 (-20.0963, 14.9735)
  point P19 (-20.0963, 14.9735)
  point P22 (-12, 11.2)
  point P23 (-12, 11.2)
  point P24 (-21, 11.2)
  point P25 (0, 11.3)
  point P26 (-21, 11.3)
  point P7 (-19.8, 4.5)
  point P27 (-19.8, 4.5)
  point P28 (-21, 4.5)
  point P14 (-19.5, 14.76)
  point P20 (-21.6, 14.7518)
  coincident L3 P8
  coincident L2 P9
  perpendicular L2 L5
  coincident L3 P10
  coincident L3 P12
  horizontal L7
  coincident L5 P15
  perpendicular L5 L8
  tangent L7 A2
  coincident P11 P18
  coincident P16 P19
  tangent A2 A3
  tangent A1 A3
  coincident P22 P23
  perpendicular L3 L10
  coincident L3 P24
  coincident L2 P25
  coincident L3 P26
  perpendicular L3 L11
  coincident P7 P27
  coincident L3 P28
  perpendicular L3 L12
  dimension "d1285" distance P7 L5 = 9
  dimension "d1286" distance L5 P10 = 2.4
  dimension "d1287" radius A1 = 0.85
  dimension "d1288" distance P8 L8 = 1.5
  dimension "d1291" radius A2 = 0.25
  dimension "d1293" distance P10 P14 = 1.14
  dimension "d1295" radius A3 = 1.52
  dimension "d1296" distance L3 P20 = 0.6
  dimension "d1308" distance L10 L11 = 0.1
extrude "Extrude138" new body sketch "Sketch33" profile of L3 L5 A1 L7 L8 A2 A3 against normal blind 8
extrude "Extrude137" cut sketch "Sketch33" profile of L1 L2 L3 L4 L12 against normal blind 4.35 (magnitude of "-t_sheet_MAIN / 2 - 1 mm")
mirror "Mirror8"
combine "Combine17"
rectangular_pattern "R-Pattern4" uSpaceDistance -3 vSpaceDistance 0
combine "Combine18"
combine "Combine19"
extrude "Extrude139" sketch "Sketch33" profile of L2 L3 L9 L10 L11 no distance stored
extrude "Extrude140" sketch "Sketch33" profile of L2 L3 L5 L9 L10 L11 blind 0.1
fillet "Fillet94" radius 3
fillet "Fillet95" radius 2
chamfer "Chamfer16" distance 0.9
chamfer "Chamfer17" distance 0.5
chamfer "Chamfer18" distance 0.5
chamfer "Chamfer19" distance 1.9
chamfer "Chamfer20" distance 0.4
mirror "Mirror9"
combine "Combine20"
combine "Combine21"
fillet "Fillet96" radius 1
fillet "Fillet97" radius 1
chamfer "Chamfer21" distance 0.2
chamfer "Chamfer22" distance 0.2
chamfer "Chamfer14" distance 0.9
fillet "Fillet93" radius 3
chamfer "Chamfer15" distance 0.5
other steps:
fillet "Extrude48" AlongDistance 65 (= "( nh_gantry_length * 10 + 10 ) / 2 * 1 mm") TaperAngle 0
fillet "Extrude57" TaperAngle 0
fillet "Extrude51" ProfileOffset 0.25 (= "carriage_offsets") TaperAngle 0
fillet "Extrude52" AlongDistance -20 TaperAngle 0
fillet "Extrude53" ProfileOffset 0.5 AlongDistance 5 (= "t_bearings") TaperAngle 0
fillet "Extrude54" AlongDistance -20 TaperAngle 0
fillet "Extrude55" ProfileOffset 0.5 AlongDistance 5 (= "t_bearings") TaperAngle 0
fillet "Extrude56" AlongDistance 670 (= "l_actual_complete") TaperAngle 0
fillet "Extrude58" ProfileOffset 0 Side1Offset 0 TaperAngle 0
fillet "Extrude59" ProfileOffset 0 Side1Offset 0 TaperAngle 0
fillet "Extrude60" ProfileOffset 0 Side1Offset 0 TaperAngle 0
step "Fillet30" Radius 4
fillet "Extrude61" AlongDistance 21 TaperAngle 0
step "OffsetFaces6"
fillet "Extrude62" ProfileOffset 0 Side1Offset 0 TaperAngle 0
fillet "Extrude63" AlongDistance 12 TaperAngle 0
step "Fillet31" Radius 4
step "Fillet32" Radius 1
step "Fillet35" Radius 0.5
step "Fillet36" Radius 0.5
step "Fillet37" Radius 0.5
step "Fillet38" Radius 0.5
step "Fillet39" Radius 0.2
step "OffsetFaces9" distance 3
step "Fillet63" Radius 2
step "Fillet64" Radius 1
fillet "Extrude64" Side1Offset 0 TaperAngle 0
fillet "Extrude65" ProfileOffset 0 Side1Offset 0 TaperAngle 0
fillet "Extrude66" ProfileOffset 0 Side1Offset 5 TaperAngle 0
fillet "Extrude67" Side1Offset 0 TaperAngle 0
fillet "Extrude68" AlongDistance -19 TaperAngle 0
fillet "Extrude69" ProfileOffset 0.5 AlongDistance 5 (= "t_bearings") TaperAngle 0
fillet "Extrude70" AlongDistance -26 TaperAngle 0
fillet "Extrude71" ProfileOffset 0.5 AlongDistance 5 (= "t_bearings") TaperAngle 0
fillet "Extrude74" ProfileOffset 0 AlongDistance 3 TaperAngle 0
fillet "Extrude75" ProfileOffset 0 Side1Offset 0 TaperAngle 0
fillet "Extrude76" Side1Offset 0 TaperAngle 0
fillet "Extrude77" ProfileOffset 0 Side1Offset 0 TaperAngle 0
fillet "Extrude78" AlongDistance 12 TaperAngle 0
fillet "Extrude72" ProfileOffset 0 Side1Offset 0 TaperAngle 0
step "Fillet42" Radius 4
step "OffsetFaces7" distance -1
fillet "Extrude73" AlongDistance 32 TaperAngle 0
fillet "Extrude79" AlongDistance -37 TaperAngle 0
fillet "Extrude80" Side1Offset 0.5 TaperAngle 0
step "Fillet44" Radius 3
step "Fillet45" Radius 2
step "Fillet47" Radius 3
step "Fillet48" Radius 3
step "Fillet49" Radius 1
step "Fillet50" Radius 0.5
step "Fillet51" Radius 2
step "Fillet55" Radius 3
step "Fillet57" Radius 0.5
fillet "Extrude81" Side1Offset 0 TaperAngle 0
fillet "Extrude82" Side1Offset 0 TaperAngle 0
step "Fillet52" Radius 2
step "Fillet53" Radius 2
step "Fillet54" Radius 2
step "OffsetFaces8" distance 3
step "Fillet59" Radius 2
step "Fillet60" Radius 2
step "Fillet61" Radius 1
step "Fillet65" Radius 2
step "Fillet66" Radius 4.5
step "OffsetFaces10" distance -0.5
fillet "Extrude83" Side1Offset 0 TaperAngle 0
fillet "Extrude84" TaperAngle 0
fillet "Extrude85" Side1Offset 0 TaperAngle 0
fillet "Extrude86" Side1Offset 0 TaperAngle 0
fillet "Extrude40" Side1Offset 0 TaperAngle 0
fillet "Extrude93" Side1Offset 0 TaperAngle 0
fillet "Extrude94" ProfileOffset 0 Side1Offset 0 TaperAngle 0
step "Chamfer8" leftDistance 1.5
fillet "Extrude95" Side1Offset 0 TaperAngle 0
fillet "Extrude41" Side1Offset 0 TaperAngle 0
fillet "Extrude87" AlongDistance -7 TaperAngle 0
step "Chamfer5" leftDistance 0.75
fillet "Extrude42" AlongDistance -5 TaperAngle 0
fillet "Extrude36" Side1Offset 0.5 TaperAngle 0
fillet "Extrude39" Side1Offset 1 TaperAngle 0
fillet "Extrude37" Side1Offset 0 TaperAngle 0
fillet "Extrude38" Side1Offset 0 TaperAngle 0
fillet "Extrude88" ProfileOffset 0 Side1Offset 0 TaperAngle 0
fillet "Extrude89" ProfileOffset 0 Side1Offset 0 TaperAngle 0
step "Chamfer6" leftDistance 1.5
step "Fillet67" Radius 4
step "Fillet68" Radius 2
step "Fillet69" Radius 2
step "Fillet70" Radius 4
step "Fillet71" Radius 2
step "Fillet72" Radius 35
step "Fillet73" Radius 4
step "Fillet74" Radius 1
step "Fillet78" ChordLen 4
step "Fillet79" ChordLen 1
step "Fillet80" Radius 2
fillet "Extrude90" Side1Offset 0 TaperAngle 0
step "Chamfer7" leftDistance 1.5
step "Fillet77" Radius 2
fillet "Extrude45" AlongDistance 100 TaperAngle 0
step "R-Pattern1" countU 13 (= "nh_gantry_length + 1") CountV 9 (= "nh_gantry_width + 1") uSpaceDistance 10 vSpaceDistance -10
step "R-Pattern2" uSpaceDistance 10 vSpaceDistance 10
fillet "Extrude92" TaperAngle 0

design "rct-lb-gt2-stray-idler"
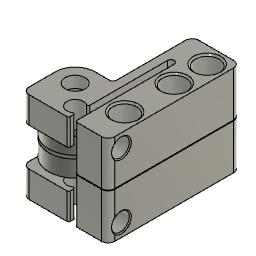
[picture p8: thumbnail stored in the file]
parameter "t_sheet_MAIN" = 6.7 comment "thickness of *most* of the gantry material"
parameter "t_sheet_SECOND" = 6.35 (= "1 / 4 * 1") comment "thickness of the webs"
parameter "od_bearings" = 16
parameter "id_bearings" = 5
parameter "t_bearings" = 5
parameter "p_belt" = 2
parameter "w_belt" = 10
parameter "t_belt" = 1.4
parameter "l_top_belt_to_rail" = 3
parameter "r_cutoutTool" = 2.05 (= "4.1 mm / 2")
parameter "hw_m3_thru" = 3.5
parameter "hw_m3_head" = 5.5
parameter "hw_m3_washer" = 7
parameter "hw_m3_thread" = 2.5
parameter "tab_breather" = 0.2 comment "tab clearance"
parameter "hw_m5_thread" = 4.2
parameter "hw_m5_head" = 8.5
parameter "hw_m5_washer" = 10
parameter "hw_m5_thru" = 5.25
parameter "hw_m6_thru" = 6.5
parameter "hw_m6_head" = 10
parameter "hw_m6_washer" = 12
parameter "l_beltblock" = 15
parameter "hw_plstf6_thread" = 2.94
parameter "hw_plstf6_thru" = 4
parameter "hw_plstf6_head" = 6.86
parameter "hw_plstf6_washer" = 7.92
parameter "hw_m3_flathead" = 6
parameter "hw_m4insert_d" = 6
parameter "hw_m4insert_l" = 4.8
parameter "hw_m4_tappedwj" = 3.3
parameter "hw_m4_thru" = 4.25
parameter "hw_m4_head" = 7
parameter "hw_m4_headheight" = 4
parameter "preload_bearings" = 0.55
parameter "hw_m3insert_d" = 5.4
parameter "hw_m3insert_l" = 3.8
parameter "dist_clearance" = 0.5
parameter "hw_shoulder_headDiameter" = 9
parameter "hw_shoulder_headHeight" = 4
parameter "l_travel" = 405 comment "will be rounded to 10s"
parameter "User Parameter" = 0 (= "min 10")
parameter "nh_rail_width" = "nh_gantry_width - 3"
parameter "l_shoulder_thread" = 10
parameter "hw_n6_thru" = 4.064
parameter "hw_n6_thread" = 3.1
parameter "hw_n6_flathead" = 6.6548
parameter "hw_n6_head" = 6.858
parameter "carriage_offsets" = 0.25
parameter "hw_momentPin_reald" = 3.683
parameter "pinch_by" = 0.2
parameter "d285" = 2
parameter "d344" = 3.5
parameter "d482" = 3.35 (= "t_sheet_MAIN / 2")
parameter "d578" = 0.5
parameter "d683" = 3.683 (= "hw_momentPin_reald")
parameter "d689" = 0.5
parameter "d698" = 5
parameter "d705" = 3.5415 (= "d683 / 2 + 1.7 mm")
parameter "d837" = 0.25
parameter "d1359" = 1.685 (= "( 3.37 / 2 ) * 1 mm")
